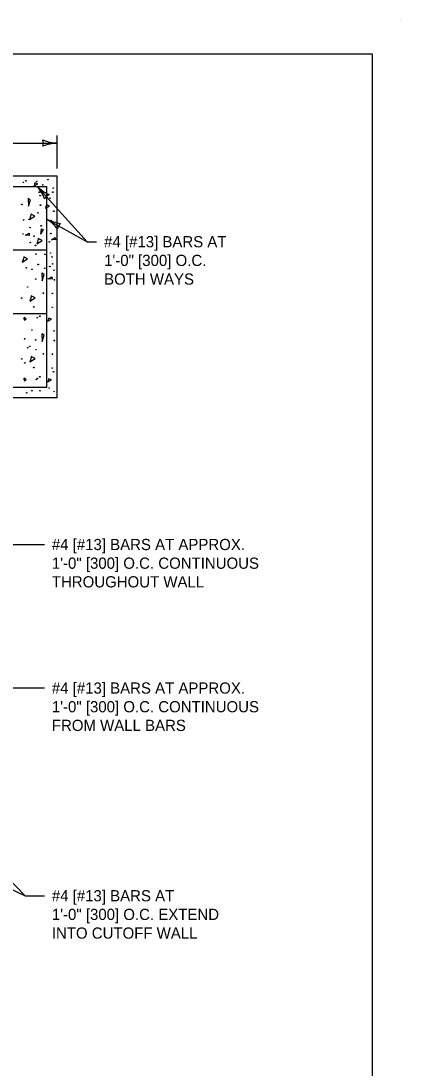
# Model space of a CAD drawing. Extents: x 49991.4 to 50021, y 49987.6 to 50011.4.
# Drawn here: x 50014.87 to 50016.9, y 49993.57 to 49999.18 of the extents above; entities that cross this region are included whole.
import ezdxf

# ---------------------------------------------------------------- set-up
doc = ezdxf.new("R2010")
doc.units = 0
for name, color, linetype in [('Level 1', 7, 'Continuous'), ('Level 2', 7, 'Continuous'), ('Level 3', 7, 'Continuous')]:
    doc.layers.add(name, color=color, linetype=linetype)

msp = doc.modelspace()

# ---------------------------------------------------------------- linework, layer by layer
at = {"layer": 'Level 1'}
for p, q in [((50016.9001, 49999.1756), (50016.9001, 49999.1756)), ((50014.0437, 49998.3456), (50015.0637, 49998.3456)), ((50015.0637, 49997.1556), (50015.0637, 49998.3456)), ((50014.1004, 49998.289), (50015.007, 49998.289)), ((50015.007, 49998.289), (50015.007, 49997.2122)), ((50014.1004, 49997.949), (50015.007, 49997.949)), ((50012.4004, 49997.609), (50015.007, 49997.609)), ((50015.007, 49997.2122), (50012.4004, 49997.2122)), ((50015.0637, 49997.1556), (50012.3438, 49997.1556))]:
    msp.add_line(p, q, dxfattribs=at)
msp.add_lwpolyline([(49999.3835, 49998.9992), (50016.7501, 49998.9992), (50016.7501, 49987.7988), (49999.3835, 49987.7988)], close=True, dxfattribs=at)
for points in [[(50014.944, 49998.3101), (50014.9397, 49998.2918), (50014.9593, 49998.3035), (50014.9433, 49998.3086)], [(50014.9075, 49998.2253), (50014.9097, 49998.183), (50014.92, 49998.2174), (50014.9082, 49998.2239)], [(50015.0068, 49998.1896), (50015.0017, 49998.1728), (50015.0222, 49998.1837), (50015.0076, 49998.1903)], [(50014.9252, 49998.1412), (50014.9158, 49998.112), (50014.9442, 49998.1302), (50014.9237, 49998.1404)], [(50014.8937, 49998.0272), (50014.9134, 49998.0389), (50014.9142, 49998.0264), (50014.8922, 49998.0286)], [(50014.9756, 49998.0332), (50014.9793, 49998.0624), (50014.9887, 49998.058), (50014.9756, 49998.0369)], [(50014.9641, 49998.0102), (50014.9547, 49997.981), (50014.9831, 49997.9992), (50014.9626, 49998.0094)], [(50015.0341, 49998.003), (50015.0538, 49998.0147), (50015.0546, 49998.0022), (50015.0326, 49998.0044)], [(50014.8862, 49997.9125), (50014.8768, 49997.8833), (50014.9052, 49997.9016), (50014.8847, 49997.9118)], [(50014.9818, 49997.8254), (50014.984, 49997.783), (50014.9943, 49997.8174), (50014.9825, 49997.8239)], [(50015.0158, 49997.7934), (50015.0355, 49997.8051), (50015.0363, 49997.7926), (50015.0143, 49997.7948)], [(50014.9263, 49997.7035), (50014.9169, 49997.6742), (50014.9453, 49997.6925), (50014.9248, 49997.7028)], [(50014.8832, 49997.587), (50014.8891, 49997.5725), (50014.8985, 49997.5804), (50014.8862, 49997.587)], [(50015.0183, 49997.5848), (50015.014, 49997.5666), (50015.0336, 49997.5782), (50015.0176, 49997.5833)], [(50014.9818, 49997.5001), (50014.984, 49997.4578), (50014.9943, 49997.4921), (50014.9825, 49997.4987)], [(50014.9263, 49997.3782), (50014.9169, 49997.349), (50014.9453, 49997.3672), (50014.9248, 49997.3774)], [(50014.8832, 49997.2617), (50014.8891, 49997.2471), (50014.8985, 49997.2551), (50014.8862, 49997.2617)], [(50015.0183, 49997.2595), (50015.014, 49997.2413), (50015.0336, 49997.253), (50015.0176, 49997.2581)]]:
    msp.add_lwpolyline(points, dxfattribs=at)
for centre in [(50014.8826, 49998.3108), (50014.8965, 49998.3192), (50014.9542, 49998.3159), (50014.9866, 49998.297), (50015.0141, 49998.3257), (50014.9672, 49998.2583), (50015.0406, 49998.2583), (50015.0428, 49998.2803), (50014.8746, 49998.1925), (50014.9724, 49998.2399), (50014.9746, 49998.1888), (50015.0255, 49998.2258), (50014.9607, 49998.1472), (50015.046, 49998.1566), (50014.884, 49998.1094), (50014.9132, 49998.1126), (50014.978, 49998.078), (50015.032, 49998.1073), (50015.046, 49998.0895), (50014.8808, 49998.034), (50014.9186, 49998.0686), (50014.9402, 49998.0225), (50015.0298, 49998.0361), (50014.9197, 49997.9879), (50014.9477, 49997.9732), (50015.0212, 49997.9921), (50014.9497, 49997.9264), (50014.9979, 49997.9249), (50015.0288, 49997.9323), (50015.0363, 49997.9114), (50014.8986, 49997.8526), (50014.9618, 49997.8705), (50014.9972, 49997.8504), (50015.0244, 49997.86), (50015.0395, 49997.8738), (50014.9284, 49997.8451), (50014.9489, 49997.7925), (50015.0467, 49997.84), (50014.9058, 49997.7502), (50015.0489, 49997.7888), (50014.8737, 49997.6903), (50014.9898, 49997.7173), (50015.038, 49997.7158), (50014.9387, 49997.6435), (50015.0373, 49997.6413), (50014.9569, 49997.5855), (50014.9708, 49997.5939), (50014.9284, 49997.5198), (50015.0467, 49997.5147), (50014.8894, 49997.4722), (50014.9489, 49997.4672), (50015.0489, 49997.4635), (50014.9058, 49997.4249), (50014.9175, 49997.4323), (50014.9499, 49997.4145), (50014.8737, 49997.365), (50014.8905, 49997.3433), (50014.9898, 49997.392), (50015.038, 49997.3905), (50014.9387, 49997.3182), (50015.0373, 49997.316), (50015.0439, 49997.2961), (50014.9521, 49997.2542), (50014.9569, 49997.2602), (50014.9708, 49997.2686), (50014.9002, 49997.1829), (50014.9284, 49997.1945), (50014.9715, 49997.1944), (50015.0201, 49997.2091), (50015.0467, 49997.1894)]:
    msp.add_circle(centre, 0.00165, dxfattribs=at)
at = {"layer": 'Level 3'}
for p, q in [((50015.0637, 49998.3856), (50015.0637, 49998.5614)), ((50012.3438, 49998.5214), (50015.0637, 49998.5214)), ((50014.957, 49998.289), (50015.2235, 49997.9927)), ((50015.007, 49998.1138), (50015.2235, 49997.9927)), ((50015.2235, 49997.9927), (50015.275, 49997.9927)), ((50014.7226, 49996.3706), (50014.9952, 49996.3706)), ((50014.9952, 49995.6016), (50014.7361, 49995.6016)), ((50014.8919, 49994.4888), (50014.6072, 49994.7813)), ((50014.4259, 49994.711), (50014.8919, 49994.4888)), ((50014.8919, 49994.4888), (50014.9952, 49994.4888))]:
    msp.add_line(p, q, dxfattribs=at)
for centre, radius, start, end in [((50015.0728, 49998.7435), 0.2223, 247.456, 267.6395), ((50014.9354, 49998.5214), 0.0548, 342.1388, 17.8612), ((50015.0752, 49998.2887), 0.233, 92.8273, 112.0772), ((50014.7888, 49998.1436), 0.2223, 20.6587, 40.8422), ((50015.1187, 49998.4567), 0.233, 226.03, 245.2799), ((50015.0447, 49998.1955), 0.0548, 115.3415, 151.0639), ((50014.89, 49997.9247), 0.2223, 38.0661, 58.2496), ((50015.1112, 49998.3222), 0.233, 243.4374, 262.6873), ((50015.1187, 49998.0509), 0.0548, 132.7489, 168.4713)]:
    msp.add_arc(centre, radius, start, end, dxfattribs=at)

# ---------------------------------------------------------------- texts
at = {"layer": 'Level 2'}
for s, p in [('#4 [#13] BARS AT', (50015.315, 49997.9627)), ('1\'-0" [300] O.C.', (50015.315, 49997.8627)), ('BOTH WAYS', (50015.315, 49997.7627)), ('#4 [#13] BARS AT APPROX.', (50015.0352, 49996.3406)), ('1\'-0" [300] O.C. CONTINUOUS', (50015.0352, 49996.2406)), ('THROUGHOUT WALL', (50015.0352, 49996.1406)), ('#4 [#13] BARS AT APPROX.', (50015.0352, 49995.5716)), ('1\'-0" [300] O.C. CONTINUOUS ', (50015.0352, 49995.4716)), ('FROM WALL BARS', (50015.0352, 49995.3716)), ('#4 [#13] BARS AT', (50015.0352, 49994.4588)), ('1\'-0" [300] O.C. EXTEND', (50015.0352, 49994.3588)), ('INTO CUTOFF WALL', (50015.0352, 49994.2588))]:
    msp.add_text(s, height=0.06, dxfattribs=at).set_placement(p)

doc.saveas('drawing.dxf')
